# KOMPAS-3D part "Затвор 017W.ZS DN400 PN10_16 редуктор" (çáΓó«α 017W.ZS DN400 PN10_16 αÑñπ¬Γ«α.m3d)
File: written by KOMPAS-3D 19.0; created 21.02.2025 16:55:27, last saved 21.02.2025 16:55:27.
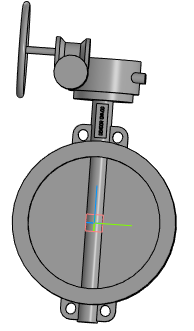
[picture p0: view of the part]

Document properties: Автор: Евгений; Полное имя файла: Затвор 017W.ZS DN400 PN10_16 редуктор.a3d

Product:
- Part/product: Затвор 017W.ZS DN400 PN10_16 редуктор
    Масса: 127.276

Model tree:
1. Операция без истории:1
